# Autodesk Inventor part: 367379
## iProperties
Created: 2006-06
Part Number: 367379
Document SubType Name: Modeling
Designer: I.Baliuc
Material: 8.8
Description: Bohrschraube
Density: 7.85 g/cm^3
Mass: 1.56272 g
Surface Area: 2.76675 cm^2
Volume: 0.199072 cm^3
HalbzeugNorm: DIN 7504 P
Abmessung: ST 4.2x13 H
Author: T.Messerschmitt
Comments: DIN 7504 P - ST 4.2x13 H
Revision Number: 367379
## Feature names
1. Basis1
